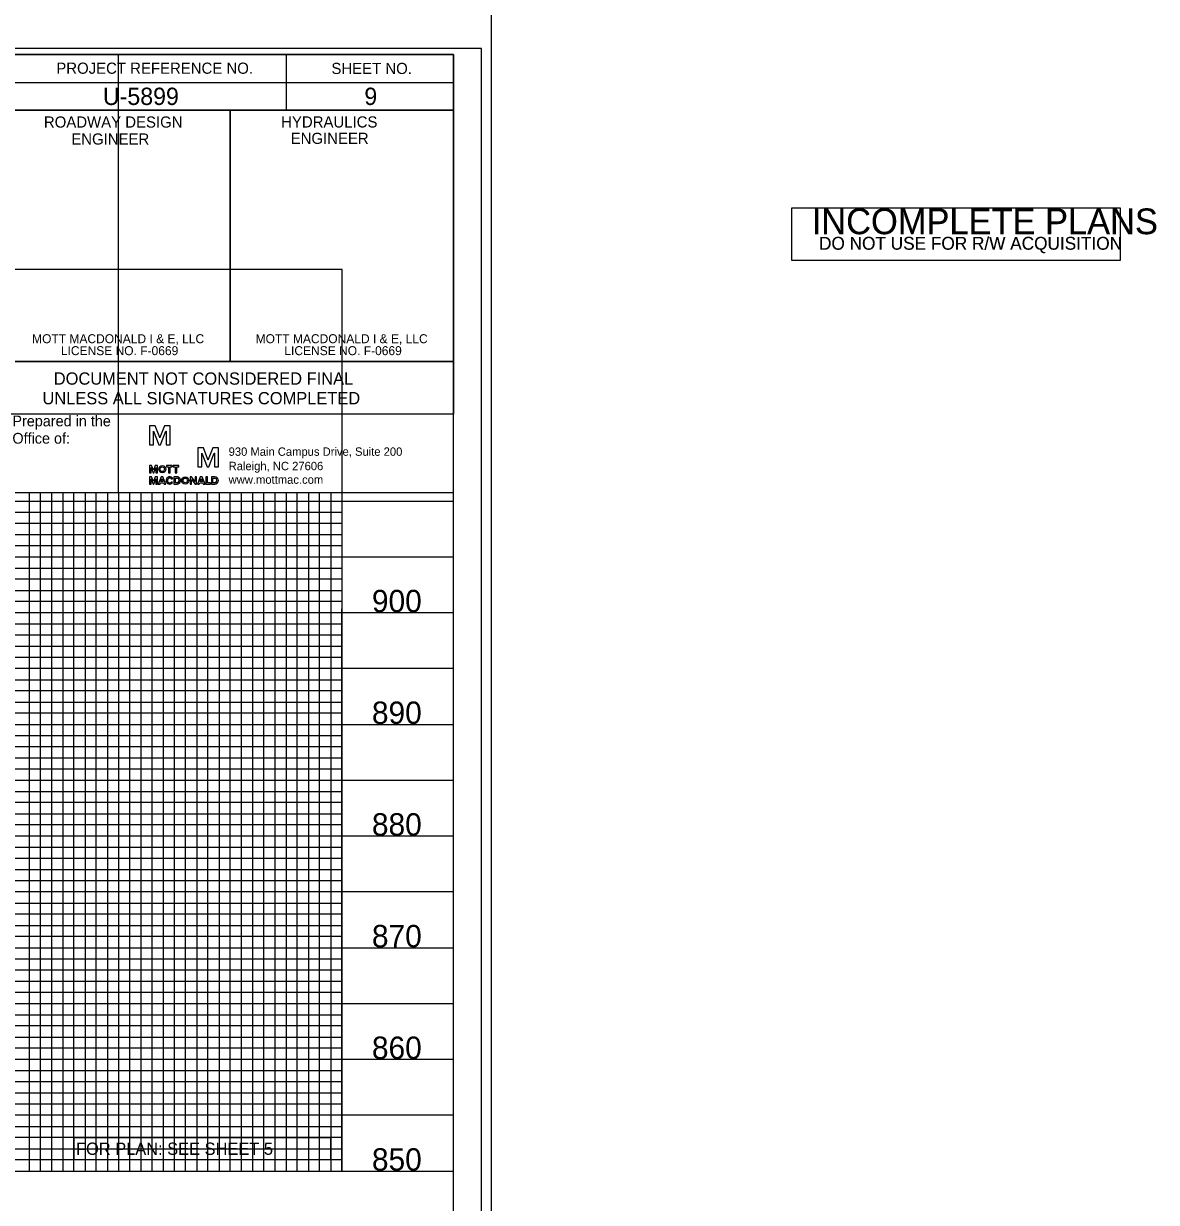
# Model space of a CAD drawing. Extents: x 1967929 to 1975641, y 546296 to 568534.
# Drawn here: x 1971339 to 1971846, y 566895 to 567423 of the extents above; entities that cross this region are included whole.
import ezdxf

# ---------------------------------------------------------------- set-up
doc = ezdxf.new("R2010")
doc.units = 0
for name, color, linetype in [('Exist Vertical Profile Vertical Axis Label', 7, 'Continuous'), ('Old_Level_2', 7, 'Continuous'), ('Old_Level_42', 7, 'Continuous'), ('Old_Level_45', 7, 'Continuous'), ('Prop Grid Mask', 7, 'Continuous'), ('Scratch_Level_1', 7, 'Continuous'), ('Scratch_Level_3', 7, 'Continuous'), ('Sheet Plot Border Inside CELL', 7, 'Continuous'), ('Sheet Plot Border Outside CELL', 7, 'Continuous'), ('Sheet Profile CELL', 7, 'Continuous'), ('Sheet Profile Grid Major CELL', 7, 'Continuous'), ('Sheet Profile Grid Middle CELL', 7, 'Continuous'), ('Sheet Profile Grid Minor CELL', 7, 'Continuous'), ('Sheet Sticker Incomplete CELL', 7, 'Continuous')]:
    doc.layers.add(name, color=color, linetype=linetype)

msp = doc.modelspace()

# ---------------------------------------------------------------- linework, layer by layer
at = {"layer": 'Old_Level_2'}
for p, q in [((1971397.84, 567242.55), (1971395.31, 567242.55)), ((1971395.31, 567242.55), (1971395.31, 567234.05)), ((1971399.89, 567237.3), (1971397.84, 567242.55)), ((1971401.99, 567242.55), (1971399.94, 567237.3)), ((1971404.52, 567242.55), (1971401.99, 567242.55)), ((1971404.52, 567234.05), (1971404.52, 567242.55)), ((1971397.11, 567234.05), (1971397.11, 567240.16)), ((1971397.11, 567240.16), (1971397.13, 567240.16)), ((1971397.13, 567240.16), (1971399.52, 567234.05)), ((1971399.89, 567237.22), (1971399.89, 567237.3)), ((1971399.94, 567237.22), (1971399.89, 567237.22)), ((1971399.94, 567237.3), (1971399.94, 567237.22)), ((1971400.3, 567234.05), (1971402.7, 567240.19)), ((1971402.7, 567240.19), (1971402.72, 567240.19)), ((1971402.72, 567240.19), (1971402.72, 567234.05)), ((1971395.31, 567234.05), (1971397.11, 567234.05)), ((1971399.52, 567234.05), (1971400.3, 567234.05)), ((1971402.72, 567234.05), (1971404.52, 567234.05)), ((1971419.45, 567232.65), (1971416.93, 567232.65)), ((1971416.93, 567232.65), (1971416.93, 567224.15)), ((1971421.5, 567227.4), (1971419.45, 567232.65)), ((1971423.61, 567232.65), (1971421.56, 567227.4)), ((1971426.13, 567232.65), (1971423.61, 567232.65)), ((1971426.13, 567224.15), (1971426.13, 567232.65)), ((1971418.72, 567224.15), (1971418.72, 567230.26)), ((1971418.72, 567230.26), (1971418.75, 567230.26)), ((1971418.75, 567230.26), (1971421.14, 567224.15)), ((1971421.5, 567227.32), (1971421.5, 567227.4)), ((1971421.56, 567227.32), (1971421.5, 567227.32)), ((1971421.56, 567227.4), (1971421.56, 567227.32)), ((1971421.92, 567224.15), (1971424.31, 567230.28)), ((1971424.31, 567230.28), (1971424.34, 567230.28)), ((1971424.34, 567230.28), (1971424.34, 567224.15)), ((1971396.28, 567224.74), (1971395.31, 567224.74)), ((1971395.31, 567224.74), (1971395.31, 567221.5)), ((1971395.31, 567221.5), (1971395.99, 567221.5)), ((1971395.99, 567221.5), (1971395.99, 567223.84)), ((1971395.99, 567223.84), (1971396.02, 567223.84)), ((1971396.02, 567223.84), (1971396.93, 567221.5)), ((1971397.08, 567222.72), (1971396.28, 567224.74)), ((1971396.93, 567221.5), (1971397.24, 567221.5)), ((1971397.89, 567224.74), (1971397.08, 567222.72)), ((1971397.24, 567221.5), (1971398.15, 567223.84)), ((1971398.85, 567224.74), (1971397.89, 567224.74)), ((1971398.15, 567223.84), (1971398.17, 567223.84)), ((1971398.15, 567223.84), (1971398.17, 567223.84)), ((1971398.17, 567223.84), (1971398.17, 567221.5)), ((1971398.17, 567221.5), (1971398.85, 567221.5)), ((1971398.85, 567221.5), (1971398.85, 567224.74)), ((1971408.54, 567224.5), (1971408.56, 567224.5)), ((1971416.93, 567224.15), (1971418.72, 567224.15)), ((1971421.14, 567224.15), (1971421.92, 567224.15)), ((1971424.34, 567224.15), (1971426.13, 567224.15)), ((1971396.28, 567219.7), (1971395.31, 567219.7)), ((1971395.31, 567219.7), (1971395.31, 567216.45)), ((1971395.31, 567216.45), (1971395.99, 567216.45)), ((1971395.99, 567216.45), (1971395.99, 567218.79)), ((1971395.99, 567218.79), (1971396.02, 567218.79)), ((1971396.02, 567218.79), (1971396.93, 567216.45)), ((1971397.08, 567217.67), (1971396.28, 567219.7)), ((1971396.93, 567216.45), (1971397.24, 567216.45)), ((1971397.89, 567219.7), (1971397.08, 567217.67)), ((1971397.24, 567216.45), (1971398.15, 567218.79)), ((1971398.85, 567219.7), (1971397.89, 567219.7)), ((1971398.15, 567218.79), (1971398.17, 567218.79)), ((1971398.17, 567218.79), (1971398.17, 567216.45)), ((1971398.17, 567216.45), (1971398.85, 567216.45)), ((1971398.85, 567216.45), (1971398.85, 567219.7)), ((1971405.67, 567217.12), (1971405.11, 567217.4)), ((1971405.19, 567218.64), (1971405.76, 567218.9)), ((1971407.69, 567219.7), (1971406.2, 567219.7)), ((1971406.2, 567219.7), (1971406.2, 567218.02)), ((1971406.2, 567218.02), (1971406.2, 567216.45)), ((1971406.2, 567216.45), (1971407.69, 567216.45)), ((1971406.88, 567217.08), (1971406.88, 567219.1)), ((1971406.88, 567219.1), (1971407.69, 567219.1)), ((1971407.69, 567217.08), (1971406.88, 567217.08)), ((1971423.02, 567219.7), (1971423.02, 567219.7)), ((1971424.51, 567219.7), (1971423.02, 567219.7)), ((1971423.02, 567219.7), (1971423.02, 567218.02)), ((1971423.02, 567218.02), (1971423.02, 567216.45)), ((1971423.02, 567216.45), (1971424.51, 567216.45)), ((1971423.7, 567217.08), (1971423.7, 567219.1)), ((1971423.7, 567219.1), (1971424.51, 567219.1)), ((1971424.51, 567217.08), (1971423.7, 567217.08)), ((1971424.51, 567219.08), (1971424.51, 567219.08))]:
    msp.add_line(p, q, dxfattribs=at)
for points in [[(1971402.93, 567224.15), (1971403.87, 567224.15), (1971403.87, 567221.5), (1971404.57, 567221.5), (1971404.57, 567224.15), (1971405.5, 567224.15), (1971405.5, 567224.74), (1971402.93, 567224.74), (1971402.93, 567224.15)], [(1971405.92, 567224.15), (1971406.85, 567224.15), (1971406.85, 567221.5), (1971407.56, 567221.5), (1971407.56, 567224.15), (1971408.49, 567224.15), (1971408.49, 567224.74), (1971405.92, 567224.74), (1971405.92, 567224.15)], [(1971399.24, 567216.45), (1971400.02, 567216.45), (1971400.23, 567217), (1971401.63, 567217), (1971401.84, 567216.45), (1971402.59, 567216.45), (1971401.34, 567219.7), (1971400.49, 567219.7), (1971399.24, 567216.45)], [(1971400.41, 567217.6), (1971400.93, 567219), (1971401.45, 567217.6), (1971400.41, 567217.6)], [(1971414.16, 567218.56), (1971414.19, 567218.56), (1971415.75, 567216.45), (1971416.4, 567216.45), (1971416.39, 567219.7), (1971415.72, 567219.7), (1971415.72, 567217.65), (1971414.18, 567219.7), (1971413.51, 567219.7), (1971413.51, 567216.45), (1971414.16, 567216.45), (1971414.16, 567218.56)], [(1971416.81, 567216.45), (1971417.59, 567216.45), (1971417.8, 567217), (1971419.2, 567217), (1971419.41, 567216.45), (1971420.16, 567216.45), (1971418.92, 567219.7), (1971418.06, 567219.7), (1971416.81, 567216.45)], [(1971417.98, 567217.6), (1971418.5, 567219), (1971419.02, 567217.6), (1971417.98, 567217.6)], [(1971422.63, 567216.45), (1971422.63, 567217.03), (1971421.23, 567217.02), (1971421.23, 567219.7), (1971420.55, 567219.7), (1971420.55, 567216.45), (1971422.63, 567216.45)]]:
    msp.add_lwpolyline(points, dxfattribs=at)
msp.add_arc((1971424.51, 567218.08), 1.62, 270, 90, dxfattribs=at)
for centre, major_axis, ratio in [((1971401.06, 567223.12), (0, 1.62), 0.993118), ((1971401.06, 567223.12), (0, 1.06), 0.916103), ((1971411.33, 567218.08), (0, 1.62), 0.993118), ((1971411.33, 567218.08), (0, 1.06), 0.916103)]:
    msp.add_ellipse(centre, major_axis=major_axis, ratio=ratio, dxfattribs=at)
for centre, major_axis, ratio, start_param, end_param in [((1971404.37, 567218.08), (0, 1.62), 0.993118, 5.246647, 10.366427), ((1971404.37, 567218.08), (0, 1.06), 0.916103, 5.276876, 10.296021), ((1971407.69, 567218.08), (0, -1.62), 0.930276, 0, 3.141593), ((1971407.69, 567218.09), (0, -1.01), 0.900832, 0, 3.141593), ((1971424.51, 567218.09), (0, -1.01), 0.900832, 0, 3.141593)]:
    msp.add_ellipse(centre, major_axis=major_axis, ratio=ratio, start_param=start_param, end_param=end_param, dxfattribs=at)
at = {"layer": 'Old_Level_42'}
msp.add_lwpolyline([(1971531.45, 567212.51), (1971331.4, 567212.51), (1971331.4, 567247.81)], dxfattribs=at)
at = {"layer": 'Prop Grid Mask'}
msp.add_lwpolyline([(1971361.53, 566923.9), (1971476.41, 566923.9), (1971476.41, 566913.87), (1971361.53, 566913.87)], close=True, dxfattribs=at)
at = {"layer": 'Scratch_Level_1'}
for p, q in [((1971331.4, 567271.31), (1971531.44, 567271.31)), ((1971531.44, 567271.3), (1971531.44, 567247.8)), ((1971531.44, 567247.81), (1971331.4, 567247.81))]:
    msp.add_line(p, q, dxfattribs=at)
at = {"layer": 'Scratch_Level_3'}
for points in [[(1970081.45, 567508.86), (1970081.45, 567008.86), (1971481.45, 567008.86), (1971481.5, 567312.53), (1971331.45, 567312.51), (1971331.4, 567508.86)], [(1970081.45, 567408.86), (1970081.45, 566908.86), (1971481.45, 566908.86), (1971481.5, 567212.51), (1971331.45, 567212.51), (1971331.4, 567408.86)], [(1970631.45, 567408.86), (1970631.45, 566908.86), (1971531.45, 566908.86), (1971531.45, 567212.52), (1971381.45, 567212.51), (1971381.45, 567408.86)]]:
    msp.add_lwpolyline(points, close=True, dxfattribs=at)
at = {"layer": 'Sheet Plot Border Inside CELL'}
msp.add_lwpolyline([(1969877.45, 566356.31), (1971543.95, 566356.31), (1971543.95, 567411.41), (1969877.45, 567411.41)], close=True, dxfattribs=at)
at = {"layer": 'Sheet Plot Border Outside CELL'}
msp.add_lwpolyline([(1969864.45, 566333.86), (1971548.45, 566333.86), (1971548.45, 567433.86), (1969864.45, 567433.86)], close=True, dxfattribs=at)
at = {"layer": 'Sheet Profile CELL'}
for p, q in [((1971456.45, 567408.81), (1971456.45, 567383.81)), ((1971331.4, 567396.31), (1971531.45, 567396.31)), ((1971431.45, 567383.81), (1971431.45, 567271.36)), ((1970031.45, 566908.86), (1971531.45, 566908.86))]:
    msp.add_line(p, q, dxfattribs=at)
for points in [[(1971531.45, 567408.86), (1970031.45, 567408.86), (1970031.45, 566358.86), (1971531.45, 566358.86)], [(1971331.4, 567408.86), (1971531.45, 567408.86), (1971531.45, 567383.81), (1971331.4, 567383.81)], [(1971331.4, 567383.81), (1971431.45, 567383.81), (1971431.45, 567271.31), (1971331.4, 567271.31)], [(1971431.45, 567383.81), (1971531.45, 567383.81), (1971531.45, 567271.31), (1971431.45, 567271.31)]]:
    msp.add_lwpolyline(points, close=True, dxfattribs=at)
msp.add_lwpolyline([(1971531.45, 567212.51), (1971331.4, 567212.51), (1971331.4, 567247.81)], dxfattribs=at)
at = {"layer": 'Sheet Profile Grid Major CELL'}
for points in [[(1971381.45, 567212.51), (1971381.45, 566908.86), (1971431.45, 566908.86), (1971431.45, 567212.51)], [(1971481.45, 567212.51), (1971481.45, 566908.86), (1971531.45, 566908.86)], [(1971531.45, 567158.86), (1970031.45, 567158.86), (1970031.45, 567208.86), (1971331.4, 567208.86)], [(1971531.45, 567158.86), (1970031.45, 567158.86), (1970031.45, 567208.86), (1971531.45, 567208.86)], [(1971381.45, 567177.21), (1971381.45, 566908.86), (1971431.45, 566908.86), (1971431.45, 567177.21)], [(1971481.45, 567177.21), (1971481.45, 566908.86), (1971531.45, 566908.86)], [(1971531.45, 567058.86), (1970031.45, 567058.86), (1970031.45, 567108.86), (1971531.45, 567108.86)], [(1971531.45, 566958.86), (1970031.45, 566958.86), (1970031.45, 567008.86), (1971531.45, 567008.86)]]:
    msp.add_lwpolyline(points, dxfattribs=at)
at = {"layer": 'Sheet Profile Grid Middle CELL'}
for points in [[(1971331.45, 567233.86), (1970031.45, 567233.86), (1970031.45, 567183.86), (1971531.45, 567183.86)], [(1971356.45, 567212.51), (1971356.45, 566908.86), (1971406.45, 566908.86), (1971406.45, 567212.51)], [(1971456.45, 567212.51), (1971456.45, 566908.86)], [(1971356.45, 567177.21), (1971356.45, 566908.86), (1971406.45, 566908.86), (1971406.45, 567177.21)], [(1971456.45, 567177.21), (1971456.45, 566908.86)], [(1971531.45, 567133.86), (1970031.45, 567133.86), (1970031.45, 567083.86), (1971531.45, 567083.86)], [(1971531.45, 567033.86), (1970031.45, 567033.86), (1970031.45, 566983.86), (1971531.45, 566983.86)], [(1971531.45, 566933.86), (1970031.45, 566933.86)]]:
    msp.add_lwpolyline(points, dxfattribs=at)
at = {"layer": 'Sheet Profile Grid Minor CELL'}
for points in [[(1971341.45, 567212.51), (1971341.45, 566908.86), (1971346.45, 566908.86), (1971346.45, 567212.51)], [(1971351.45, 567212.51), (1971351.45, 566908.86), (1971361.45, 566908.86), (1971361.45, 567212.51)], [(1971366.45, 567212.51), (1971366.45, 566908.86), (1971371.45, 566908.86), (1971371.45, 567212.51)], [(1971376.45, 567212.51), (1971376.45, 566908.86), (1971386.45, 566908.86), (1971386.45, 567212.51)], [(1971391.45, 567212.51), (1971391.45, 566908.86), (1971396.45, 566908.86), (1971396.45, 567212.51)], [(1971401.45, 567212.51), (1971401.45, 566908.86), (1971411.45, 566908.86), (1971411.45, 567212.51)], [(1971416.45, 567212.51), (1971416.45, 566908.86)], [(1971416.45, 566908.86), (1971421.45, 566908.86), (1971421.45, 567212.51)], [(1971426.45, 567212.51), (1971426.45, 566908.86), (1971436.45, 566908.86), (1971436.45, 567212.51)], [(1971441.45, 567212.51), (1971441.45, 566908.86), (1971446.45, 566908.86), (1971446.45, 567212.51)], [(1971451.45, 567212.51), (1971451.45, 566908.86), (1971461.45, 566908.86), (1971461.45, 567212.51)], [(1971466.45, 567212.51), (1971466.45, 566908.86), (1971471.45, 566908.86), (1971471.45, 567212.51)], [(1971476.45, 567212.51), (1971476.45, 566908.86), (1971486.45, 566908.86)], [(1970631.45, 567203.86), (1971481.45, 567203.86)], [(1971481.45, 567198.86), (1970631.45, 567198.86)], [(1970631.45, 567193.86), (1971481.45, 567193.86)], [(1971481.45, 567188.86), (1970631.45, 567188.86)], [(1970631.45, 567178.86), (1971481.45, 567178.86)], [(1971481.45, 567173.86), (1970631.45, 567173.86)], [(1971341.45, 567177.21), (1971341.45, 566908.86), (1971346.45, 566908.86), (1971346.45, 567177.21)], [(1971351.45, 567177.21), (1971351.45, 566908.86), (1971361.45, 566908.86), (1971361.45, 567177.21)], [(1971366.45, 567177.21), (1971366.45, 566908.86), (1971371.45, 566908.86), (1971371.45, 567177.21)], [(1971376.45, 567177.21), (1971376.45, 566908.86), (1971386.45, 566908.86), (1971386.45, 567177.21)], [(1971391.45, 567177.21), (1971391.45, 566908.86), (1971396.45, 566908.86), (1971396.45, 567177.21)], [(1971401.45, 567177.21), (1971401.45, 566908.86), (1971411.45, 566908.86), (1971411.45, 567177.21)], [(1971416.45, 567177.21), (1971416.45, 566908.86)], [(1971416.45, 566908.86), (1971421.45, 566908.86), (1971421.45, 567177.21)], [(1971426.45, 567177.21), (1971426.45, 566908.86), (1971436.45, 566908.86), (1971436.45, 567177.21)], [(1971441.45, 567177.21), (1971441.45, 566908.86), (1971446.45, 566908.86), (1971446.45, 567177.21)], [(1971451.45, 567177.21), (1971451.45, 566908.86), (1971461.45, 566908.86), (1971461.45, 567177.21)], [(1971466.45, 567177.21), (1971466.45, 566908.86), (1971471.45, 566908.86), (1971471.45, 567177.21)], [(1971476.45, 567177.21), (1971476.45, 566908.86), (1971486.45, 566908.86)], [(1970631.45, 567168.86), (1971481.45, 567168.86)], [(1971481.45, 567163.86), (1970631.45, 567163.86)], [(1970631.45, 567153.86), (1971481.45, 567153.86)], [(1971481.45, 567148.86), (1970631.45, 567148.86)], [(1970631.45, 567143.86), (1971481.45, 567143.86)], [(1971481.45, 567138.86), (1970631.45, 567138.86)], [(1970631.45, 567128.86), (1971481.45, 567128.86)], [(1971481.45, 567123.86), (1970631.45, 567123.86)], [(1970631.45, 567118.86), (1971481.45, 567118.86)], [(1971481.45, 567113.86), (1970631.45, 567113.86)], [(1970631.45, 567103.86), (1971481.45, 567103.86)], [(1971481.45, 567098.86), (1970631.45, 567098.86)], [(1970631.45, 567093.86), (1971481.45, 567093.86)], [(1971481.45, 567088.86), (1970631.45, 567088.86)], [(1970631.45, 567078.86), (1971481.45, 567078.86)], [(1971481.45, 567073.86), (1970631.45, 567073.86)], [(1970631.45, 567068.86), (1971481.45, 567068.86)], [(1971481.45, 567063.86), (1970631.45, 567063.86)], [(1970631.45, 567053.86), (1971481.45, 567053.86)], [(1971481.45, 567048.86), (1970631.45, 567048.86)], [(1970631.45, 567043.86), (1971481.45, 567043.86)], [(1971481.45, 567038.86), (1970631.45, 567038.86)], [(1970631.45, 567028.86), (1971481.45, 567028.86)], [(1971481.45, 567023.86), (1970631.45, 567023.86)], [(1970631.45, 567018.86), (1971481.45, 567018.86)], [(1971481.45, 567013.86), (1970631.45, 567013.86)], [(1970631.45, 567003.86), (1971481.45, 567003.86)], [(1971481.45, 566998.86), (1970631.45, 566998.86)], [(1970631.45, 566993.86), (1971481.45, 566993.86)], [(1971481.45, 566988.86), (1970631.45, 566988.86)], [(1970631.45, 566978.86), (1971481.45, 566978.86)], [(1971481.45, 566973.86), (1970631.45, 566973.86)], [(1970631.45, 566968.86), (1971481.45, 566968.86)], [(1971481.45, 566963.86), (1970631.45, 566963.86)], [(1970631.45, 566953.86), (1971481.45, 566953.86)], [(1971481.45, 566948.86), (1970631.45, 566948.86)], [(1970631.45, 566943.86), (1971481.45, 566943.86)], [(1971481.45, 566938.86), (1970631.45, 566938.86)], [(1970631.45, 566928.86), (1971481.45, 566928.86)], [(1971481.45, 566923.86), (1970631.45, 566923.86)], [(1970631.45, 566918.86), (1971481.45, 566918.86)], [(1970531.45, 566913.86), (1970081.45, 566913.86), (1970081.45, 566908.86), (1971481.45, 566908.86)], [(1971481.45, 566913.86), (1970631.45, 566913.86)]]:
    msp.add_lwpolyline(points, dxfattribs=at)
at = {"layer": 'Sheet Sticker Incomplete CELL'}
for points in [[(1971682.78, 567316.64), (1971682.78, 567340.14), (1971829.78, 567340.14), (1971829.78, 567316.64)], [(1971682.86, 567316.64), (1971682.86, 567340.14), (1971829.86, 567340.14), (1971829.86, 567316.64)]]:
    msp.add_lwpolyline(points, close=True, dxfattribs=at)

# ---------------------------------------------------------------- texts
at = {"layer": 'Exist Vertical Profile Vertical Axis Label'}
for s, p in [('900', (1971494.88, 567159.11)), ('890', (1971494.88, 567109.11)), ('880', (1971494.88, 567059.11)), ('870', (1971494.88, 567009.11)), ('860', (1971494.88, 566959.11)), ('850', (1971494.88, 566909.11))]:
    msp.add_text(s, height=10, dxfattribs=at).set_placement(p)
at = {"layer": 'Old_Level_2'}
for s, height, p in [('Prepared in the ', 4.8186, (1971333.95, 567242.31)), ('Office of:', 4.819, (1971333.95, 567234.56))]:
    msp.add_text(s, height=height, dxfattribs=at).set_placement(p)
for s, p in [('930 Main Campus Drive, Suite 200', (1971430.73, 567229.13)), ('Raleigh, NC 27606', (1971430.73, 567222.68)), ('www.mottmac.com', (1971430.73, 567216.59))]:
    msp.add_text(s, height=3.75, rotation=360, dxfattribs=at).set_placement(p)
at = {"layer": 'Old_Level_45'}
for s, p in [('MOTT MACDONALD I & E, LLC', (1971342.76, 567279.54)), ('MOTT MACDONALD I & E, LLC', (1971442.81, 567279.54)), (' LICENSE NO. F-0669', (1971354.15, 567274.19)), (' LICENSE NO. F-0669', (1971454.2, 567274.19))]:
    msp.add_text(s, height=4.0179, dxfattribs=at).set_placement(p)
at = {"layer": 'Prop Grid Mask'}
msp.add_text('FOR PLAN: SEE SHEET 5', height=5.4932, dxfattribs=at).set_placement((1971362.42, 566916.16))
at = {"layer": 'Scratch_Level_1'}
for s, p in [('DOCUMENT NOT CONSIDERED FINAL', (1971352.47, 567260.97)), ('UNLESS ALL SIGNATURES COMPLETED', (1971347.4, 567252.17))]:
    msp.add_text(s, height=5.5, dxfattribs=at).set_placement(p)
at = {"layer": 'Sheet Profile CELL'}
for s, height, p in [('PROJECT REFERENCE NO.', 5.0001, (1971353.6, 567400.16)), ('SHEET NO.', 5, (1971476.75, 567400.06)), ('U-5899', 7.75, (1971374.47, 567386.19)), ('9', 7.75, (1971491.49, 567386.19)), ('ROADWAY DESIGN', 5.0001, (1971348.05, 567376.06)), ('HYDRAULICS', 5, (1971454.25, 567376.11)), ('ENGINEER', 5, (1971360.3, 567368.46)), ('ENGINEER', 5, (1971458.5, 567368.76))]:
    msp.add_text(s, height=height, dxfattribs=at).set_placement(p)
at = {"layer": 'Sheet Sticker Incomplete CELL'}
for s, height, p in [('INCOMPLETE PLANS', 11.52, (1971691.73, 567328.34)), ('INCOMPLETE PLANS', 11.52, (1971691.81, 567328.34)), ('DO NOT USE FOR R/W ACQUISITION', 5.76, (1971694.98, 567321.39)), ('DO NOT USE FOR R/W ACQUISITION', 5.76, (1971695.06, 567321.39))]:
    msp.add_text(s, height=height, dxfattribs=at).set_placement(p)

doc.saveas('drawing.dxf')
